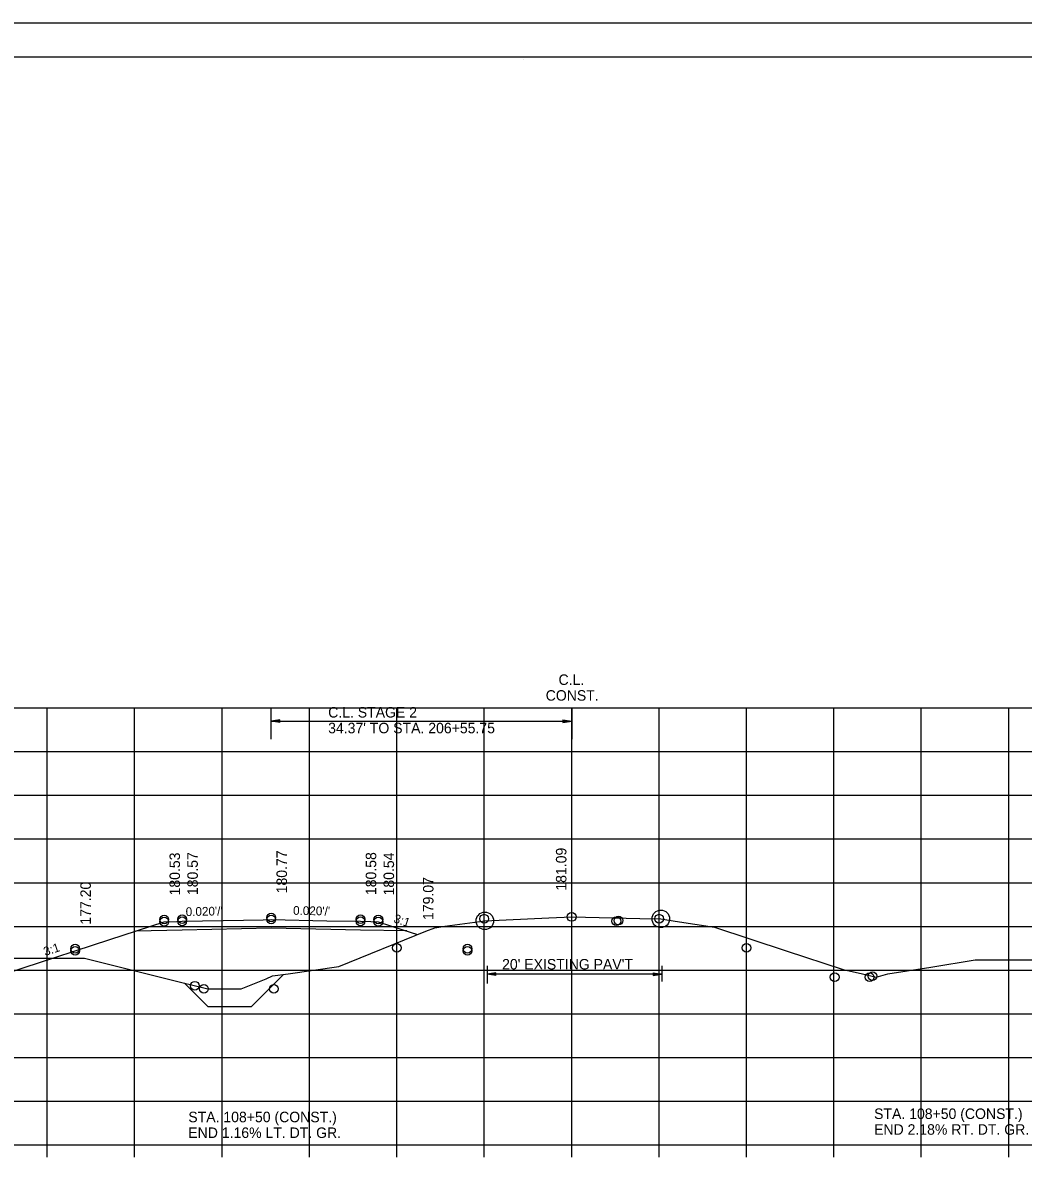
# Model space of a CAD drawing. Extents: x 1372132 to 1372465, y 380083 to 381790.
# Drawn here: x 1372239.2 to 1372353.7, y 381233.1 to 381363.5 of the extents above; entities that cross this region are included whole.
import ezdxf

# ---------------------------------------------------------------- set-up
doc = ezdxf.new("R2010")
doc.units = 0
for name, color, linetype in [('R_Alt Surface', 7, 'Continuous'), ('R_Axis', 7, 'Continuous'), ('R_Border', 7, 'Continuous'), ('R_Draft', 7, 'Continuous'), ('R_Erosion', 7, 'Continuous'), ('R_Exist Surface', 7, 'Continuous'), ('R_Fin Surface', 7, 'Continuous'), ('R_Grid', 7, 'Continuous'), ('R_No Plot', 7, 'Continuous'), ('R_Xsect Elev', 7, 'Continuous'), ('R_Xsect Slope', 7, 'Continuous')]:
    doc.layers.add(name, color=color, linetype=linetype)

msp = doc.modelspace()

# ---------------------------------------------------------------- linework, layer by layer
at = {"layer": 'R_Alt Surface'}
msp.add_lwpolyline([(1372283.15, 381259.64), (1372277.85, 381259.74), (1372267.64, 381259.94), (1372257.44, 381259.74), (1372252.14, 381259.63)], dxfattribs=at)
at = {"layer": 'R_Axis'}
for p, q in [((1372162.01, 381235.16), (1372442.01, 381235.16)), ((1372242.01, 381233.76), (1372242.01, 381235.16)), ((1372252.01, 381233.76), (1372252.01, 381235.16)), ((1372262.01, 381233.76), (1372262.01, 381235.16)), ((1372272.01, 381233.76), (1372272.01, 381235.16)), ((1372282.01, 381233.76), (1372282.01, 381235.16)), ((1372292.01, 381233.76), (1372292.01, 381235.16)), ((1372302.01, 381233.76), (1372302.01, 381235.16)), ((1372312.01, 381233.76), (1372312.01, 381235.16)), ((1372322.01, 381233.76), (1372322.01, 381235.16)), ((1372332.01, 381233.76), (1372332.01, 381235.16)), ((1372342.01, 381233.76), (1372342.01, 381235.16)), ((1372352.01, 381233.76), (1372352.01, 381235.16))]:
    msp.add_line(p, q, dxfattribs=at)
at = {"layer": 'R_Border'}
for p, q in [((1372144.01, 381359.62), (1372460.19, 381359.62)), ((1372296.53, 381359.36), (1372296.53, 381359.36)), ((1372296.53, 381359.36), (1372296.53, 381359.36))]:
    msp.add_line(p, q, dxfattribs=at)
at = {"layer": 'R_Draft'}
for p, q in [((1372267.64, 381281.57), (1372267.64, 381285.16)), ((1372302.01, 381285.16), (1372302.01, 381281.57)), ((1372268.64, 381283.8), (1372267.64, 381283.65)), ((1372267.64, 381283.65), (1372302.01, 381283.65)), ((1372268.64, 381283.5), (1372267.64, 381283.65)), ((1372268.64, 381283.78), (1372267.81, 381283.65)), ((1372268.64, 381283.53), (1372267.81, 381283.65)), ((1372268.64, 381283.75), (1372267.98, 381283.65)), ((1372268.64, 381283.55), (1372267.98, 381283.65)), ((1372268.64, 381283.73), (1372268.15, 381283.65)), ((1372268.64, 381283.58), (1372268.15, 381283.65)), ((1372268.64, 381283.7), (1372268.32, 381283.65)), ((1372268.64, 381283.6), (1372268.32, 381283.65)), ((1372268.64, 381283.68), (1372268.49, 381283.65)), ((1372268.64, 381283.63), (1372268.49, 381283.65)), ((1372268.64, 381283.5), (1372268.64, 381283.8)), ((1372301.01, 381283.8), (1372302.01, 381283.65)), ((1372301.01, 381283.8), (1372301.01, 381283.5)), ((1372301.01, 381283.8), (1372302.01, 381283.65)), ((1372301.01, 381283.8), (1372301.01, 381283.5)), ((1372301.01, 381283.78), (1372301.85, 381283.65)), ((1372301.01, 381283.78), (1372301.85, 381283.65)), ((1372301.01, 381283.75), (1372301.68, 381283.65)), ((1372301.01, 381283.75), (1372301.68, 381283.65)), ((1372301.01, 381283.73), (1372301.51, 381283.65)), ((1372301.01, 381283.73), (1372301.51, 381283.65)), ((1372301.01, 381283.7), (1372301.34, 381283.65)), ((1372301.01, 381283.7), (1372301.34, 381283.65)), ((1372301.01, 381283.68), (1372301.17, 381283.65)), ((1372301.01, 381283.68), (1372301.17, 381283.65)), ((1372301.01, 381283.5), (1372302.01, 381283.65)), ((1372301.01, 381283.6), (1372301.34, 381283.65)), ((1372301.01, 381283.55), (1372301.68, 381283.65)), ((1372301.01, 381283.53), (1372301.85, 381283.65)), ((1372301.01, 381283.58), (1372301.51, 381283.65)), ((1372301.01, 381283.63), (1372301.17, 381283.65)), ((1372301.01, 381283.5), (1372302.01, 381283.65)), ((1372301.01, 381283.6), (1372301.34, 381283.65)), ((1372301.01, 381283.55), (1372301.68, 381283.65)), ((1372301.01, 381283.53), (1372301.85, 381283.65)), ((1372301.01, 381283.58), (1372301.51, 381283.65)), ((1372301.01, 381283.63), (1372301.17, 381283.65)), ((1372292.35, 381255.63), (1372292.35, 381253.62)), ((1372293.35, 381254.86), (1372292.35, 381254.71)), ((1372293.35, 381254.86), (1372292.35, 381254.71)), ((1372312.33, 381254.71), (1372292.35, 381254.71)), ((1372293.35, 381254.56), (1372292.35, 381254.71)), ((1372293.35, 381254.56), (1372292.35, 381254.71)), ((1372293.35, 381254.84), (1372292.52, 381254.71)), ((1372293.35, 381254.84), (1372292.52, 381254.71)), ((1372293.35, 381254.59), (1372292.52, 381254.71)), ((1372293.35, 381254.59), (1372292.52, 381254.71)), ((1372293.35, 381254.81), (1372292.69, 381254.71)), ((1372293.35, 381254.81), (1372292.69, 381254.71)), ((1372293.35, 381254.61), (1372292.69, 381254.71)), ((1372293.35, 381254.61), (1372292.69, 381254.71)), ((1372293.35, 381254.79), (1372292.85, 381254.71)), ((1372293.35, 381254.79), (1372292.85, 381254.71)), ((1372293.35, 381254.64), (1372292.85, 381254.71)), ((1372293.35, 381254.64), (1372292.85, 381254.71)), ((1372293.35, 381254.76), (1372293.02, 381254.71)), ((1372293.35, 381254.76), (1372293.02, 381254.71)), ((1372293.35, 381254.66), (1372293.02, 381254.71)), ((1372293.35, 381254.66), (1372293.02, 381254.71)), ((1372293.35, 381254.73), (1372293.19, 381254.71)), ((1372293.35, 381254.73), (1372293.19, 381254.71)), ((1372293.35, 381254.69), (1372293.19, 381254.71)), ((1372293.35, 381254.69), (1372293.19, 381254.71)), ((1372293.35, 381254.56), (1372293.35, 381254.86)), ((1372293.35, 381254.56), (1372293.35, 381254.86)), ((1372311.33, 381254.86), (1372312.33, 381254.71)), ((1372311.33, 381254.86), (1372311.33, 381254.56)), ((1372311.33, 381254.84), (1372312.16, 381254.71)), ((1372311.33, 381254.81), (1372311.99, 381254.71)), ((1372311.33, 381254.79), (1372311.82, 381254.71)), ((1372311.33, 381254.76), (1372311.65, 381254.71)), ((1372311.33, 381254.73), (1372311.49, 381254.71)), ((1372311.33, 381254.56), (1372312.33, 381254.71)), ((1372311.33, 381254.66), (1372311.65, 381254.71)), ((1372311.33, 381254.61), (1372311.99, 381254.71)), ((1372311.33, 381254.59), (1372312.16, 381254.71)), ((1372311.33, 381254.64), (1372311.82, 381254.71)), ((1372311.33, 381254.69), (1372311.49, 381254.71)), ((1372312.33, 381255.63), (1372312.33, 381253.85)), ((1372292.35, 381253.85), (1372292.35, 381253.85))]:
    msp.add_line(p, q, dxfattribs=at)
at = {"layer": 'R_Erosion'}
for p, q in [((1372265.38, 381251.01), (1372269.04, 381254.67)), ((1372260.37, 381251.01), (1372257.72, 381253.66)), ((1372260.37, 381251.01), (1372265.38, 381251.01))]:
    msp.add_line(p, q, dxfattribs=at)
at = {"layer": 'R_Exist Surface'}
msp.add_lwpolyline([(1372236.05, 381256.54), (1372246.27, 381256.51), (1372257.27, 381253.77), (1372260.38, 381253), (1372263.35, 381253.03), (1372264.19, 381253.02), (1372267.04, 381254.18), (1372267.77, 381254.5), (1372269.59, 381254.75), (1372275.37, 381255.59), (1372285.33, 381259.61), (1372286.34, 381260.01), (1372287.5, 381260.17), (1372292.08, 381260.79), (1372299.4, 381261.14), (1372302.01, 381261.25), (1372309.79, 381261.07), (1372312.21, 381261.02), (1372313.84, 381260.77), (1372318.35, 381260.09), (1372326.56, 381257.35), (1372333.06, 381255.22), (1372335.3, 381254.74), (1372336.86, 381254.35), (1372338.2, 381254.73), (1372343.09, 381255.5), (1372348.18, 381256.33), (1372373.04, 381256.32)], dxfattribs=at)
at = {"layer": 'R_Fin Surface'}
msp.add_lwpolyline([(1372236.11, 381254.39), (1372239.36, 381255.46), (1372242.87, 381256.6), (1372245.2, 381257.36), (1372249.19, 381258.67), (1372255.4, 381260.7), (1372256.82, 381260.72), (1372257.44, 381260.74), (1372264.48, 381260.88), (1372266.73, 381260.92), (1372267.64, 381260.94), (1372273.99, 381260.81), (1372277.85, 381260.74), (1372279.03, 381260.72), (1372279.89, 381260.7), (1372282.69, 381259.78), (1372284.37, 381259.23)], dxfattribs=at)
at = {"layer": 'R_Grid'}
for p, q in [((1372162.01, 381285.16), (1372442.01, 381285.16)), ((1372242.01, 381235.16), (1372242.01, 381285.16)), ((1372252.01, 381235.16), (1372252.01, 381285.16)), ((1372262.01, 381235.16), (1372262.01, 381285.16)), ((1372272.01, 381235.16), (1372272.01, 381285.16)), ((1372282.01, 381235.16), (1372282.01, 381285.16)), ((1372292.01, 381235.16), (1372292.01, 381285.16)), ((1372302.01, 381235.16), (1372302.01, 381285.16)), ((1372312.01, 381235.16), (1372312.01, 381285.16)), ((1372322.01, 381235.16), (1372322.01, 381285.16)), ((1372332.01, 381235.16), (1372332.01, 381285.16)), ((1372342.01, 381235.16), (1372342.01, 381285.16)), ((1372352.01, 381235.16), (1372352.01, 381285.16)), ((1372162.01, 381280.16), (1372442.01, 381280.16)), ((1372162.01, 381275.16), (1372442.01, 381275.16)), ((1372162.01, 381270.16), (1372442.01, 381270.16)), ((1372162.01, 381265.16), (1372442.01, 381265.16)), ((1372162.01, 381260.16), (1372442.01, 381260.16)), ((1372162.01, 381255.16), (1372442.01, 381255.16)), ((1372162.01, 381250.16), (1372442.01, 381250.16)), ((1372162.01, 381245.16), (1372442.01, 381245.16)), ((1372162.01, 381240.16), (1372442.01, 381240.16)), ((1372162.01, 381235.16), (1372442.01, 381235.16))]:
    msp.add_line(p, q, dxfattribs=at)
at = {"layer": 'R_No Plot'}
msp.add_line((1372131.61, 381363.52), (1372464.95, 381363.52), dxfattribs=at)
for points in [[(1372131.61, 381363.52), (1372464.95, 381363.52), (1372464.95, 381150.18), (1372131.61, 381150.18)], [(1372377.93, 381359.62), (1372377.93, 381349.74), (1372413.67, 381349.74), (1372413.67, 381346.82), (1372436.87, 381346.82), (1372436.87, 381322.49), (1372460.19, 381322.49), (1372460.19, 381154.16), (1372144.01, 381154.16), (1372144.01, 381359.62)]]:
    msp.add_lwpolyline(points, close=True, dxfattribs=at)
for centre, radius in [((1372255.4, 381260.94), 0.5), ((1372255.4, 381260.7), 0.5), ((1372257.44, 381260.98), 0.5), ((1372257.44, 381260.74), 0.5), ((1372267.64, 381261.18), 0.5), ((1372267.64, 381260.94), 0.5), ((1372277.85, 381260.98), 0.5), ((1372277.85, 381260.74), 0.5), ((1372279.89, 381260.94), 0.5), ((1372279.89, 381260.7), 0.5), ((1372292.08, 381260.79), 1), ((1372292, 381261.04), 0.5), ((1372292.01, 381261.04), 0.5), ((1372302.01, 381261.24), 0.5), ((1372307.12, 381260.77), 0.5), ((1372307.36, 381260.82), 0.5), ((1372312.21, 381261.02), 1), ((1372312.01, 381261.04), 0.5), ((1372312.02, 381261.04), 0.5), ((1372245.2, 381257.61), 0.5), ((1372245.2, 381257.36), 0.5), ((1372282, 381257.71), 0.5), ((1372290.09, 381257.61), 0.5), ((1372290.09, 381257.37), 0.5), ((1372322.02, 381257.71), 0.5), ((1372332.1, 381254.35), 0.5), ((1372336.1, 381254.35), 0.5), ((1372336.42, 381254.46), 0.5), ((1372258.89, 381253.37), 0.5), ((1372259.94, 381253.02), 0.5), ((1372267.94, 381253.02), 0.5)]:
    msp.add_circle(centre, radius, dxfattribs=at)
at = {"layer": 'R_Xsect Elev'}
msp.add_line((1372302.01, 381261.25), (1372302.01, 381271.25), dxfattribs=at)

# ---------------------------------------------------------------- texts
at = {"layer": 'R_Draft'}
for s, p in [('C.L. ', (1372300.51, 381287.78)), ('CONST. ', (1372299.04, 381285.98)), ('C.L. STAGE 2', (1372274.15, 381284.05)), ("34.37' TO STA. 206+55.75", (1372274.15, 381282.25)), ("20' EXISTING PAV'T", (1372294.05, 381255.23))]:
    msp.add_text(s, height=1.2, rotation=360, dxfattribs=at).set_placement(p)
for s, p in [('STA. 108+50 (CONST.)', (1372258.15, 381237.76)), ('STA. 108+50 (CONST.)', (1372336.61, 381238.13)), ('END 1.16% LT. DT. GR.', (1372258.15, 381235.96)), ('END 2.18% RT. DT. GR.', (1372336.61, 381236.33))]:
    msp.add_text(s, height=1.2, dxfattribs=at).set_placement(p)
at = {"layer": 'R_Xsect Elev'}
for s, p in [('181.09', (1372301.41, 381264.25)), ('180.53', (1372257.2, 381263.7)), ('180.57', (1372259.24, 381263.74)), ('180.77', (1372269.44, 381263.94)), ('180.58', (1372279.65, 381263.74)), ('180.54', (1372281.69, 381263.7)), ('177.20', (1372247, 381260.36)), ('179.07', (1372286.2, 381260.89))]:
    msp.add_text(s, height=1.2, rotation=90, dxfattribs=at).set_placement(p)
at = {"layer": 'R_Xsect Slope'}
for s, rotation, p in [("0.020'/'", 1.1284, (1372257.86, 381261.34)), ("0.020'/'", 358.8827, (1372270.13, 381261.49)), ('3:1', 341.9147, (1372281.57, 381260.64)), ('3:1', 18.0817, (1372241.77, 381256.77))]:
    msp.add_text(s, height=1, rotation=rotation, dxfattribs=at).set_placement(p)

doc.saveas('drawing.dxf')
